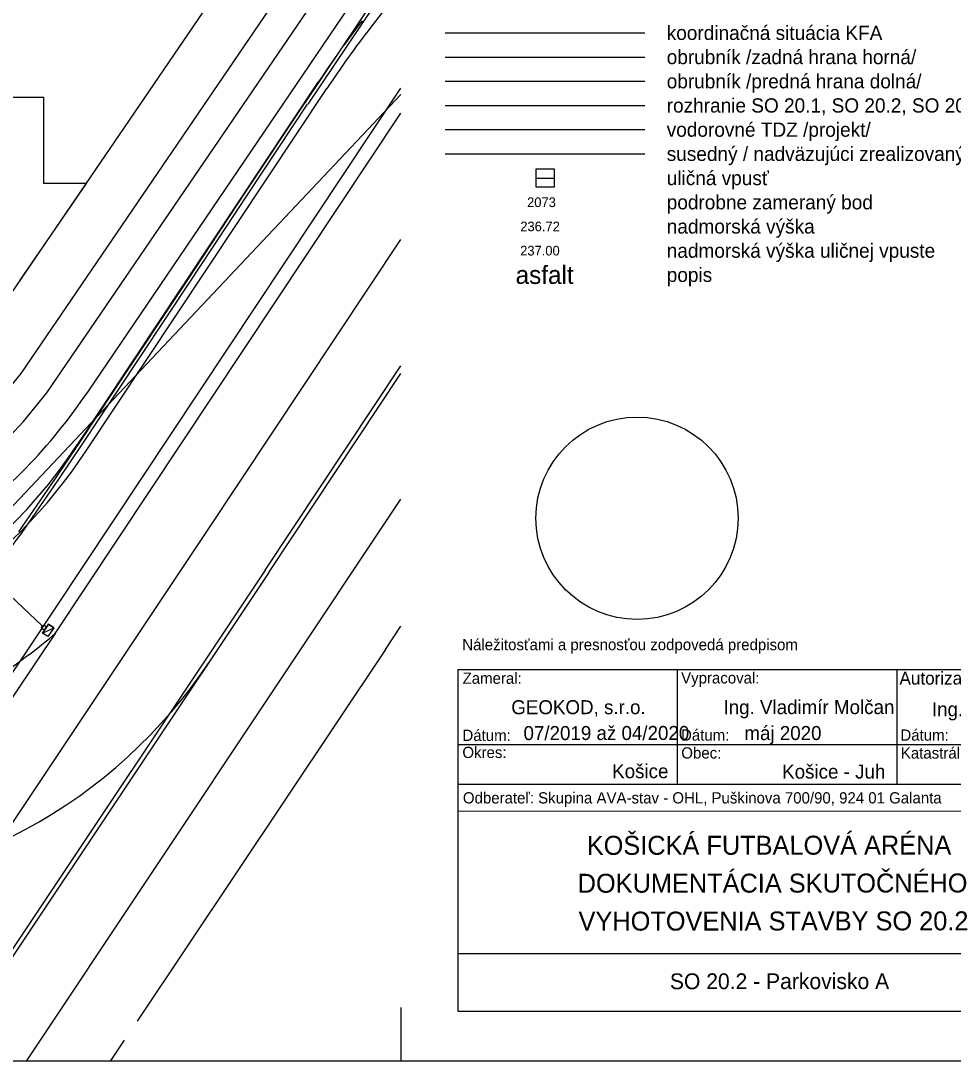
# Model space of a CAD drawing. Extents: x -264165 to -263733, y -1242319 to -1242245.
# Drawn here: x -263798.04 to -263754.68, y -1242319.19 to -1242270.82 of the extents above; entities that cross this region are included whole.
import ezdxf

# ---------------------------------------------------------------- set-up
doc = ezdxf.new("R2010")
doc.units = 0
for name, color, linetype in [('LEGENDA', 7, 'Continuous'), ('PROJEKT_OBRUBNIKY_KOMUNIKACIE', 7, 'Continuous'), ('PROJEKT_TDZ_VODOROVNE', 7, 'Continuous'), ('RAM_NA_TLAC_1-250', 7, 'Continuous'), ('ROZPISKA', 7, 'Continuous'), ('SITUACIA_DSP_2D', 7, 'Continuous'), ('SO_20-1_OBRUBNIKY_DOLNA_HRANA', 7, 'Continuous'), ('SO_20-1_OBRUBNIKY_HORNA_HRANA', 7, 'Continuous')]:
    doc.layers.add(name, color=color, linetype=linetype)

msp = doc.modelspace()

# ---------------------------------------------------------------- linework, layer by layer
at = {"layer": 'LEGENDA'}
for p, q in [((-263778.299, -1242271.381), (-263769.016, -1242271.381)), ((-263778.299, -1242272.506), (-263769.016, -1242272.506)), ((-263778.299, -1242273.631), (-263769.016, -1242273.631)), ((-263778.299, -1242274.756), (-263769.016, -1242274.756)), ((-263778.299, -1242275.881), (-263769.016, -1242275.881)), ((-263778.299, -1242277.006), (-263769.016, -1242277.006))]:
    msp.add_line(p, q, dxfattribs=at)
for points in [[(-263774.079, -1242277.709), (-263773.235, -1242277.709), (-263773.235, -1242278.553), (-263774.079, -1242278.553)], [(-263774.079, -1242278.553), (-263774.079, -1242277.709)], [(-263774.079, -1242278.131), (-263773.235, -1242278.131)]]:
    msp.add_lwpolyline(points, dxfattribs=at)
at = {"layer": 'PROJEKT_OBRUBNIKY_KOMUNIKACIE'}
for p, q in [((-263798.899, -1242284.125), (-263780.363, -1242256.915)), ((-263794.898, -1242288.032), (-263780.363, -1242266.607)), ((-263795.416, -1242290.541), (-263784.213, -1242273.68))]:
    msp.add_line(p, q, dxfattribs=at)
msp.add_lwpolyline([(-263798.064, -1242282.882), (-263794.987, -1242278.383), (-263796.968, -1242278.382), (-263796.968, -1242274.382), (-263799.468, -1242274.382), (-263799.468, -1242270.382), (-263791.968, -1242270.382), (-263791.968, -1242266.382), (-263796.968, -1242266.382), (-263796.968, -1242260.382), (-263791.968, -1242260.382), (-263791.968, -1242258.382), (-263799.468, -1242258.382), (-263799.468, -1242265.987), (-263802.068, -1242265.987)], dxfattribs=at)
for centre, radius, start, end in [((-263742.568, -1242301.35), 50, 142.3688, 146.3992), ((-263816.067, -1242273.815), 25.5, 305.2702, 326.1165), ((-263815.822, -1242276.982), 24.5, 270, 326.3992)]:
    msp.add_arc(centre, radius, start, end, dxfattribs=at)
at = {"layer": 'PROJEKT_TDZ_VODOROVNE'}
for p, q in [((-263780.363, -1242269.302), (-263781.759, -1242271.113)), ((-263795, -1242290.817), (-263783.807, -1242273.971)), ((-263796.435, -1242299.302), (-263780.363, -1242275.114)), ((-263789.385, -1242294.564), (-263780.363, -1242280.987)), ((-263786.678, -1242296.363), (-263780.363, -1242286.859)), ((-263786.512, -1242296.474), (-263780.363, -1242287.22)), ((-263797.781, -1242319.185), (-263780.363, -1242293.051)), ((-263805.817, -1242319.185), (-263789.385, -1242294.564)), ((-263786.678, -1242296.363), (-263801.914, -1242319.185)), ((-263786.512, -1242296.474), (-263801.673, -1242319.185)), ((-263796.435, -1242299.302), (-263802.558, -1242308.383)), ((-263781.086, -1242300.054), (-263780.363, -1242298.967)), ((-263781.086, -1242300.054), (-263792.626, -1242317.328)), ((-263793.865, -1242319.185), (-263793.213, -1242318.207))]:
    msp.add_line(p, q, dxfattribs=at)
for points in [[(-263816.072, -1242319.185), (-263814.291, -1242315.804), (-263813.06, -1242301.353), (-263812.968, -1242299.181), (-263802.618, -1242291.831), (-263801.478, -1242290.893), (-263800.257, -1242289.755), (-263799.049, -1242288.464), (-263798.027, -1242287.218), (-263780.363, -1242261.313)], [(-263814.635, -1242319.185), (-263813.062, -1242316.188), (-263811.682, -1242301.389), (-263811.608, -1242300.055), (-263801.705, -1242293.023), (-263800.489, -1242292.021), (-263799.197, -1242290.817), (-263797.92, -1242289.454), (-263796.825, -1242288.118), (-263780.363, -1242263.975)]]:
    msp.add_lwpolyline(points, dxfattribs=at)
for centre, radius, start, end in [((-263742.161, -1242301.641), 50, 142.3688, 146.3992), ((-263815.822, -1242276.982), 25, 282.7622, 326.3992), ((-263816.477, -1242275.476), 31.135, 289.1139, 310.0684), ((-263809.228, -1242287.295), 24, 270.4085, 326.3969)]:
    msp.add_arc(centre, radius, start, end, dxfattribs=at)
at = {"layer": 'RAM_NA_TLAC_1-250'}
msp.add_line((-263780.363, -1242316.685), (-263780.363, -1242319.185), dxfattribs=at)
msp.add_lwpolyline([(-264165.363, -1242244.935), (-263732.863, -1242244.935), (-263732.863, -1242319.185), (-264165.363, -1242319.185)], close=True, dxfattribs=at)
at = {"layer": 'ROZPISKA'}
for p, q in [((-263777.719, -1242300.974), (-263777.72, -1242316.856)), ((-263777.719, -1242300.974), (-263735.749, -1242300.973)), ((-263767.512, -1242300.973), (-263767.509, -1242306.308)), ((-263757.303, -1242300.975), (-263757.3, -1242306.305)), ((-263777.721, -1242304.459), (-263747.092, -1242304.459)), ((-263777.72, -1242306.305), (-263747.093, -1242306.305)), ((-263777.723, -1242307.556), (-263747.089, -1242307.552)), ((-263777.72, -1242314.178), (-263735.748, -1242314.176)), ((-263777.72, -1242316.856), (-263735.748, -1242316.856))]:
    msp.add_line(p, q, dxfattribs=at)
msp.add_circle((-263769.381, -1242293.946), 4.702, dxfattribs=at)
at = {"layer": 'SITUACIA_DSP_2D'}
for p, q in [((-263798.899, -1242284.125), (-263780.363, -1242256.915)), ((-263794.898, -1242288.032), (-263780.363, -1242266.607)), ((-263795.416, -1242290.541), (-263784.214, -1242273.68)), ((-263810.431, -1242319.185), (-263780.363, -1242273.949)), ((-263780.363, -1242274.247), (-263808.248, -1242303.783)), ((-263797.048, -1242298.952), (-263800.558, -1242295.638)), ((-263797.029, -1242299.286), (-263796.75, -1242298.871)), ((-263796.75, -1242298.871), (-263797.029, -1242299.286)), ((-263796.75, -1242298.871), (-263796.51, -1242299.032)), ((-263796.51, -1242299.032), (-263796.75, -1242298.871)), ((-263797.029, -1242299.286), (-263796.51, -1242299.032)), ((-263797.029, -1242299.286), (-263796.51, -1242299.032)), ((-263796.788, -1242299.448), (-263797.029, -1242299.286)), ((-263796.51, -1242299.032), (-263796.788, -1242299.448))]:
    msp.add_line(p, q, dxfattribs=at)
msp.add_lwpolyline([(-263798.064, -1242282.882), (-263794.987, -1242278.383), (-263796.968, -1242278.382), (-263796.968, -1242274.382), (-263799.468, -1242274.382), (-263799.468, -1242270.382), (-263791.968, -1242270.382), (-263791.968, -1242266.382), (-263796.968, -1242266.382), (-263796.968, -1242260.382), (-263791.968, -1242260.382), (-263791.968, -1242258.382), (-263799.468, -1242258.382), (-263799.468, -1242265.987), (-263802.068, -1242265.987)], dxfattribs=at)
msp.add_circle((-263796.975, -1242299.02), 0.1, dxfattribs=at)
for centre, radius, start, end in [((-263742.568, -1242301.35), 50, 142.3688, 146.3992), ((-263816.067, -1242273.815), 25.5, 305.2702, 326.1165), ((-263815.822, -1242276.982), 24.5, 270, 326.3992)]:
    msp.add_arc(centre, radius, start, end, dxfattribs=at)
at = {"layer": 'SO_20-1_OBRUBNIKY_DOLNA_HRANA'}
for points in [[(-263780.363, -1242268.244), (-263784.695, -1242274.697)], [(-263798.013, -1242294.654), (-263796.303, -1242292.18), (-263795.189, -1242290.524), (-263793.538, -1242288.034), (-263790.216, -1242283.022), (-263787.462, -1242278.872), (-263784.7, -1242274.704)]]:
    msp.add_lwpolyline(points, dxfattribs=at)
msp.add_ellipse((-263825.45, -1242274.928), major_axis=(18.854, 28.266), ratio=0.994545, start_param=4.514508, end_param=4.677485, dxfattribs=at)
at = {"layer": 'SO_20-1_OBRUBNIKY_HORNA_HRANA'}
for points in [[(-263784.822, -1242274.627), (-263781.463, -1242269.63), (-263780.363, -1242267.997)], [(-263798.132, -1242294.573), (-263796.423, -1242292.099), (-263795.31, -1242290.444), (-263793.659, -1242287.955), (-263790.34, -1242282.948), (-263787.584, -1242278.79), (-263784.82, -1242274.623)]]:
    msp.add_lwpolyline(points, dxfattribs=at)

# ---------------------------------------------------------------- texts
at = {"layer": 'LEGENDA'}
for s, height, p in [('koordinačná situácia KFA', 0.66129, (-263768.001, -1242271.711)), ('obrubník /zadná hrana horná/', 0.66129, (-263768.001, -1242272.836)), ('obrubník /predná hrana dolná/', 0.66129, (-263768.001, -1242273.961)), ('rozhranie SO 20.1, SO 20.2, SO 20.3', 0.66129, (-263768.001, -1242275.086)), ('vodorovné TDZ /projekt/', 0.66129, (-263768.001, -1242276.211)), ('susedný / nadväzujúci zrealizovaný SO 20.1 a SO 20.3', 0.66129, (-263768.001, -1242277.336)), ('uličná vpusť', 0.66129, (-263768.001, -1242278.461)), ('2073', 0.45, (-263774.495, -1242279.481)), ('podrobne zameraný bod', 0.66129, (-263768.001, -1242279.586)), ('nadmorská výška', 0.66129, (-263768.001, -1242280.711)), ('236.72', 0.45, (-263774.812, -1242280.606)), ('237.00', 0.45, (-263774.818, -1242281.731)), ('nadmorská výška uličnej vpuste', 0.66129, (-263768.001, -1242281.836)), ('asfalt', 0.8438, (-263775.027, -1242283.053)), ('popis', 0.6613, (-263768.001, -1242282.961))]:
    msp.add_text(s, height=height, dxfattribs=at).set_placement(p)
at = {"layer": 'ROZPISKA'}
for s, height, rotation, p in [('Náležitosťami a presnosťou zodpovedá predpisom', 0.5217, 0.0016, (-263777.51, -1242300.08)), ('Zameral:', 0.5217, 0.0016, (-263777.494, -1242301.642)), ('Vypracoval:', 0.5217, 0.0016, (-263767.332, -1242301.627)), ('Autorizačne overil:', 0.59461, 0.0016, (-263757.179, -1242301.678)), ('GEOKOD, s.r.o.', 0.65196, 0.0456, (-263775.23, -1242303.056)), ('Ing. Vladimír Molčan', 0.65209, 0.0456, (-263765.361, -1242303.054)), ('Ing. Boris Beťko', 0.65241, 0.0456, (-263755.669, -1242303.151)), ('Dátum:', 0.5217, 0.0016, (-263777.501, -1242304.299)), ('07/2019 až 04/2020', 0.65196, 0.0456, (-263774.661, -1242304.258)), ('Dátum:', 0.5217, 0.0016, (-263767.338, -1242304.285)), ('máj 2020', 0.652, 0.0456, (-263764.39, -1242304.258)), ('Dátum:', 0.5217, 0.0016, (-263757.134, -1242304.286)), ('Okres:', 0.5217, 0.0016, (-263777.504, -1242305.09)), ('Obec:', 0.5217, 0.0016, (-263767.323, -1242305.115)), ('Katastrálne územie:', 0.5217, 0.0016, (-263757.115, -1242305.117)), ('Košice', 0.6523, 0.0456, (-263770.539, -1242306.031)), ('Košice - Juh', 0.65241, 0.0456, (-263762.634, -1242306.051)), ('Odberateľ: Skupina AVA-stav - OHL, Puškinova 700/90, 924 01 Galanta', 0.52157, 0.0016, (-263777.48, -1242307.204)), ('KOŠICKÁ FUTBALOVÁ ARÉNA', 0.88076, 0.0456, (-263771.719, -1242309.593)), ('DOKUMENTÁCIA SKUTOČNÉHO', 0.88076, 0.0456, (-263772.141, -1242311.355)), ('VYHOTOVENIA STAVBY SO 20.2', 0.88076, 0.0456, (-263772.101, -1242313.116)), ('SO 20.2 - Parkovisko A', 0.73378, 0.0456, (-263767.855, -1242315.838))]:
    msp.add_text(s, height=height, rotation=rotation, dxfattribs=at).set_placement(p)

doc.saveas('drawing.dxf')
